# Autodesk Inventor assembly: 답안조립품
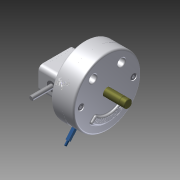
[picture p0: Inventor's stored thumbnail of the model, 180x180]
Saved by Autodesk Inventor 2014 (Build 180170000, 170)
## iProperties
Created: 2015-04
Part Number: 답안조립품
Document SubType Name: Assembly
Designer: 시험용
Author: 시험용
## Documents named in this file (15)
- C:\Users\시험용\Desktop\350405V1002\답안조립품.iam
- C:\Users\시험용\Desktop\350405V1002\본체.ipt
- C:\Users\시험용\Desktop\350405V1002\커버.ipt
- C:\Users\시험용\Desktop\350405V1002\커버2.ipt
- C:\Users\시험용\Desktop\350405V1002\베어링62_22.ipt
- C:\Users\시험용\Desktop\350405V1002\축.ipt
- C:\Users\시험용\Desktop\350405V1002\멈춤링.ipt
- C:\Users\시험용\Desktop\350405V1002\부시.ipt
- C:\Users\시험용\Desktop\350405V1002\슬라이더3.ipt
- C:\Users\시험용\Desktop\350405V1002\M 10 x 35.ipt
- C:\Users\시험용\Desktop\350405V1002\M 5 x 12.ipt
- C:\Users\시험용\Desktop\350405V1002\가변스프링.ipt
- C:\Users\시험용\Desktop\350405V1002\슬라이더2.ipt
- C:\Users\시험용\Desktop\350405V1002\평행핀.ipt
- C:\Users\시험용\Desktop\350405V1002\슬라이더.ipt
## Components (6 placed, 4 different names)
1. M 10 x 35:1
2. M 10 x 35:2
3. M 5 x 12:1
4. M 5 x 12:2
5. 가변스프링:1
6. KS B 1320 B B 5 x  20:1
